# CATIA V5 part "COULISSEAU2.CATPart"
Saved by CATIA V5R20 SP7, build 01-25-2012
Part number: COULISSEAU2
Bounding box of the stored display mesh (mm): x -20 to 20, y -82.66 to 327, z -20 to 55.557
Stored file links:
  J:\IAO_placube\COULISSEAU2.CATPart
  J:\IAO_placube\placube_assemblage_IAO.CATProduct
  J:\IAO_placube\SKL_coulisseau.CATPart
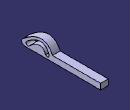
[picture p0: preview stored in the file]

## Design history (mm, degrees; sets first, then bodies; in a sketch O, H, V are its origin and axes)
Set1
  Plane1 "plan_ref": linked copy from another document
  DatumPoint1: linked copy from another document
  DatumPoint2: linked copy from another document
  DatumCurve1: linked copy from another document
  Line1: linked copy from another document
Body1 (main body)
  Sketch1 on Plane1, origin (0, 0, 0), H (0, 1, 0), V (0, 0, 1)
    spline S1 through (-56.1044, 7.9206) (45.0724, 29.2412) (59.2824, 3.988)
    spline S2 through (-43.5964, -7.6808) (33.2966, 11.4695) (41.0015, -4.5929)
    spline S3 through (-76.8619, 8.3356) (56.7264, 40.4726) (77, 10)
    reference projected point E1 (50, 0) from vertex of DatumPoint1
    reference projected point E2 (-50, 0) from vertex of DatumPoint2
    arc A1 centre (49.6879, 0.665) radius 10.1537 from (41.0015, -4.5929) to (59.2824, 3.988) ccw
    point P2 (41.0015, -4.5929)
    point P3 (59.2824, 3.988)
    arc A2 centre (-50, 0) radius 10 from (-56.1044, 7.9206) to (-43.5964, -7.6808) ccw
    point P4 (-50, 0)
    point P5 (-56.1044, 7.9206)
    point P6 (-43.5964, -7.6808)
    reference projected point E3 (-50, 0) from DatumPoint2
    arc A3 centre (-66.672, -4) radius 16 from (-76.8619, 8.3356) to (-66.672, -20) ccw
    point P7 (-76.8619, 8.3356)
    point P9 (-66.672, -20)
    line L1 (-66.672, -20) -> (327, -20)
    point P10 (-66.672, -20)
    point P11 (327, -20)
    line L2 (77, 10) -> (327, 10)
    point P12 (77, 10)
    line L3 (327, 10) -> (327, -20)
    point P14 (327, -20)
    line L4 (327, -20) -> (327, -20)
    point P15 (327, -20)
    point P16 (41.0015, -4.5929)
    point P17 (59.2824, 3.988)
    point P18 (-56.1044, 7.9206)
    point P19 (-43.5964, -7.6808)
    point P20 (45.0724, 29.2412)
    point P21 (33.2966, 11.4695)
    point P22 (-76.8619, 8.3356)
    point P23 (77, 10)
    point P24 (56.7264, 40.4726)
    distance S2 S1 = 20
    distance S1 S3 = 13.0288
    distance L1 L2 = 30
    distance L3 P12 = 250
    equidistance: P16 P17 E1, P18 P19 E2
    coincidence: P3 P17, P2 P16, P5 P18, P4 E3, P22 P7, P10 P9, P23 P12, P14 L1, P11 P15, P6 P19
    tangency: A1 S1, A3 S3, L1 A3, L2 A2, L4 A3
    fix: S1, P18, P20, P17, S2, P19, P21, P16, S3, P22, P24, P23
    horizontal: L1 H
    vertical: L3 V
  Pad1: profile Sketch1, direction (1, 0, 0), length 20, mirrored extent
